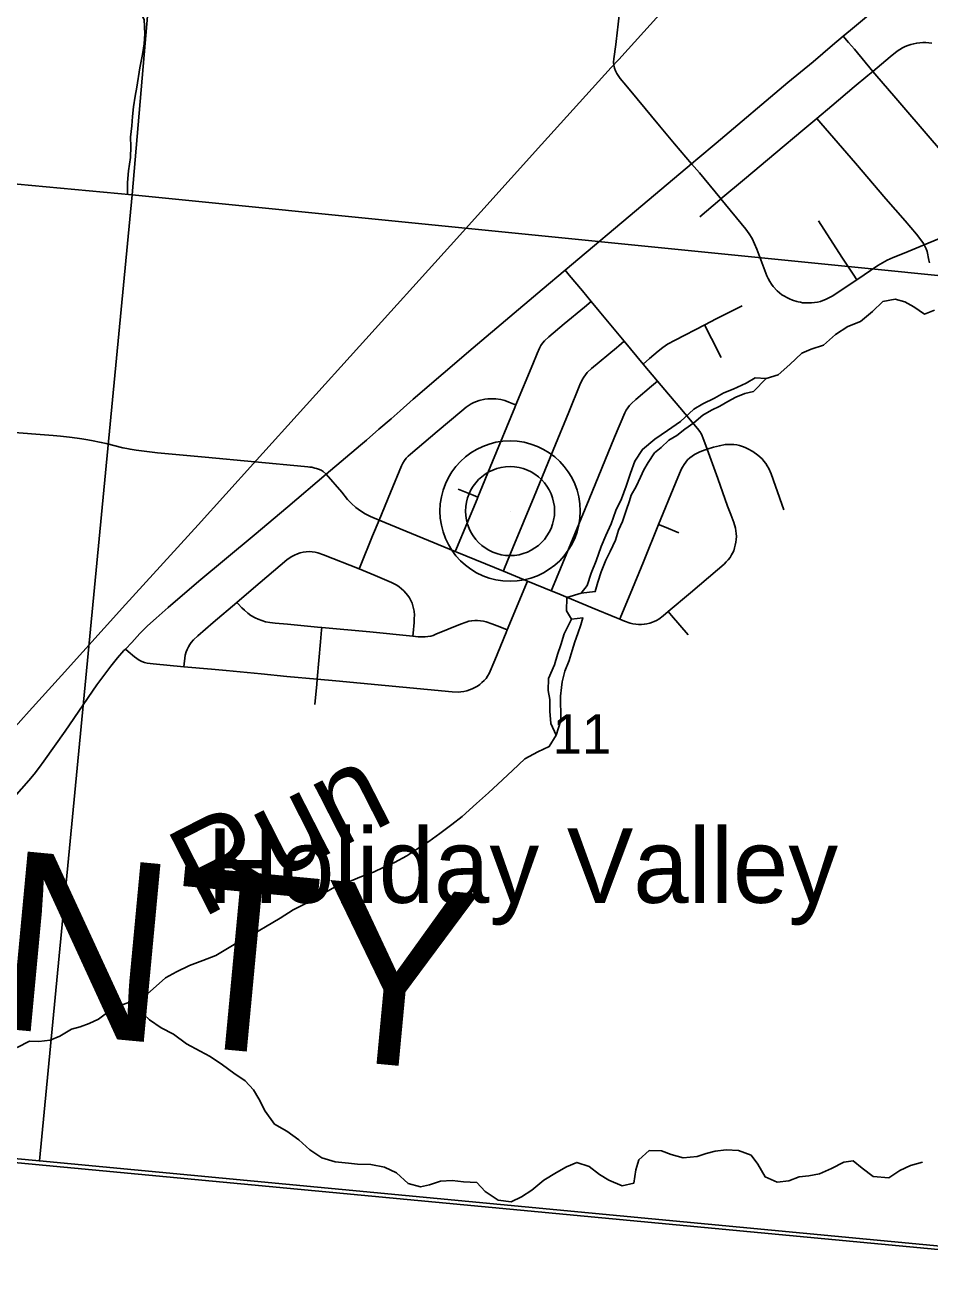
# Model space of a CAD drawing. Extents: x 0 to 1134, y 0 to 440.
# Drawn here: x 838.269 to 839.228, y 357.514 to 358.846 of the extents above; entities that cross this region are included whole.
import ezdxf

# ---------------------------------------------------------------- set-up
doc = ezdxf.new("R2010")
doc.units = 0
for name, color, linetype in [('GM_X_County_Road', 7, 'Continuous'), ('GM_X_County_Text', 7, 'Continuous'), ('GM_X_Minor_Lake', 7, 'Continuous'), ('GM_X_Minor_River', 7, 'Continuous'), ('GM_X_Minor_River_Text', 7, 'Continuous'), ('GM_X_Rail_Line', 7, 'Continuous'), ('GM_X_Section', 7, 'Continuous'), ('GM_X_Section_Text', 7, 'Continuous'), ('GM_X_Township', 7, 'Continuous'), ('GM_X_Township_Road', 7, 'Continuous'), ('GM_X_Unincorporated', 7, 'Continuous'), ('GM_X_Unincorporated_Location', 7, 'Continuous'), ('GM_X_Unincorporated_Text', 7, 'Continuous'), ('SH_Cut_Line', 7, 'Continuous')]:
    doc.layers.add(name, color=color, linetype=linetype)

msp = doc.modelspace()

# ---------------------------------------------------------------- linework, layer by layer
at = {"layer": 'GM_X_County_Road'}
for points in [[(839.1364, 358.8339), (839.1442, 358.8404), (839.2059, 358.8923), (839.2297, 358.9122), (839.2323, 358.9144)], [(838.9755, 358.6986), (838.9821, 358.7043), (839.0016, 358.7206), (839.0776, 358.7847), (839.1044, 358.8069), (839.1251, 358.8245), (839.1364, 358.8339)], [(838.8414, 358.5858), (838.9238, 358.6552), (838.9755, 358.6986)], [(838.5879, 358.3697), (838.6244, 358.4002), (838.6309, 358.4058), (838.6439, 358.4172), (838.6569, 358.4284), (838.6663, 358.4367), (838.6802, 358.4492), (838.7439, 358.5034), (838.8172, 358.5654), (838.8414, 358.5858)], [(838.2073, 358.4176), (838.2847, 358.4116), (838.2985, 358.4105), (838.3062, 358.4098), (838.3156, 358.4088), (838.3239, 358.4078), (838.3288, 358.4071), (838.333, 358.4065), (838.339, 358.4054), (838.3494, 358.4033), (838.3545, 358.4022), (838.3723, 358.3976), (838.3766, 358.3967), (838.38, 358.396), (838.3863, 358.395), (838.3949, 358.3939), (838.409, 358.3923), (838.4598, 358.3878), (838.5124, 358.3827), (838.565, 358.3779), (838.5686, 358.3775), (838.5707, 358.3772), (838.5729, 358.3769), (838.574, 358.3766), (838.575, 358.3764), (838.576, 358.3761), (838.5778, 358.3755), (838.5797, 358.3748), (838.5825, 358.3737), (838.5849, 358.3723), (838.5879, 358.3697)], [(838.375, 358.1841), (838.3817, 358.1913), (838.3905, 358.2007), (838.3986, 358.2087), (838.4076, 358.217), (838.4203, 358.2283), (838.4528, 358.2562), (838.5115, 358.3051), (838.5473, 358.335), (838.5879, 358.3697)], [(838.2572, 358.027), (838.2728, 358.0448), (838.2782, 358.0514), (838.2838, 358.0589), (838.2886, 358.0653), (838.311, 358.0972), (838.3449, 358.1461), (838.3596, 358.166), (838.3668, 358.175), (838.3735, 358.1826), (838.375, 358.1841)]]:
    msp.add_lwpolyline(points, dxfattribs=at)
at = {"layer": 'GM_X_Minor_Lake'}
for points in [[(838.8583, 358.2435), (838.8648, 358.2514), (838.8691, 358.2646), (838.8742, 358.2778), (838.8796, 358.2929), (838.8847, 358.3046), (838.8902, 358.317), (838.8952, 358.331), (838.9011, 358.3434), (838.9061, 358.357), (838.9108, 358.3706), (838.9155, 358.3834), (838.9236, 358.3958), (838.9366, 358.4066), (838.95, 358.4159), (838.9637, 358.4256), (838.9778, 358.4387), (838.9874, 358.4443), (838.9999, 358.4502), (839.0098, 358.4558), (839.0197, 358.4598), (839.0334, 358.4661), (839.0429, 358.4716), (839.0546, 358.4711)], [(838.8583, 358.2435), (838.8734, 358.2452), (838.8762, 358.2551), (838.8797, 358.266), (838.8844, 358.2784), (838.889, 358.2875), (838.8948, 358.2995), (838.898, 358.3101), (838.9023, 358.3195), (838.9062, 358.3312), (838.9097, 358.3414), (838.9113, 358.3475), (838.9167, 358.3565), (838.9214, 358.3663), (838.9249, 358.3742), (838.9295, 358.3821), (838.9361, 358.3922), (838.9433, 358.3978), (838.9513, 358.4057), (838.9597, 358.4105), (838.9685, 358.4172), (838.978, 358.4239), (838.9876, 358.4322), (838.9967, 358.4373), (839.0055, 358.4418), (839.0138, 358.4466), (839.0226, 358.4511), (839.0321, 358.4551), (839.0412, 358.4573), (839.0546, 358.4711)], [(838.8482, 358.2158), (838.8403, 358.2002), (838.8368, 358.1885), (838.8333, 358.1783), (838.8301, 358.1673), (838.8239, 358.153), (838.8233, 358.1401), (838.8251, 358.1306), (838.8253, 358.1185), (838.8263, 358.1052), (838.8318, 358.093)], [(838.8318, 358.093), (838.8369, 358.1085), (838.8367, 358.1168), (838.8364, 358.1267), (838.8365, 358.1343), (838.8374, 358.1434), (838.8382, 358.1494), (838.841, 358.1608), (838.8456, 358.1721), (838.8488, 358.1826), (838.8516, 358.1917), (838.8547, 358.2007), (838.8582, 358.2098), (838.8602, 358.2174), (838.8482, 358.2158)]]:
    msp.add_lwpolyline(points, dxfattribs=at)
at = {"layer": 'GM_X_Minor_River'}
for points in [[(838.3855, 358.8731), (838.3896, 358.8619), (838.3948, 358.8516), (838.3958, 358.8365), (838.3949, 358.8259), (838.3932, 358.8145), (838.3904, 358.8005), (838.3871, 358.7801), (838.3855, 358.7703), (838.3835, 358.759), (838.3826, 358.7487), (838.3817, 358.7389), (838.3804, 358.7268), (838.3807, 358.7169), (838.3805, 358.7052), (838.3785, 358.6912), (838.3772, 358.6787), (838.3774, 358.6662)], [(838.3272, 357.7836), (838.3367, 357.7872), (838.3466, 357.7917), (838.3592, 357.8014), (838.3725, 357.8073), (838.3831, 357.8113), (838.3956, 357.8161), (838.4078, 357.8269), (838.4174, 357.8355), (838.4292, 357.8418), (838.4429, 357.8485), (838.4573, 357.854), (838.471, 357.8591), (838.4851, 357.8677), (838.495, 357.8736), (838.5117, 357.8825), (838.5235, 357.8895), (838.5391, 357.8988), (838.5529, 357.9077), (838.5665, 357.9144), (838.5772, 357.9215), (838.5901, 357.9278), (838.6016, 357.9344), (838.6145, 357.9384), (838.6255, 357.9432), (838.638, 357.9476), (838.649, 357.9528), (838.6604, 357.958), (838.6734, 357.965), (838.6841, 357.9721), (838.697, 357.9803), (838.7084, 357.9885), (838.7214, 357.9981), (838.7321, 358.0067), (838.7474, 358.0206), (838.76, 358.0318), (838.7699, 358.0411), (838.7856, 358.0553), (838.7986, 358.0677), (838.8123, 358.0751), (838.8245, 358.081), (838.8318, 358.093), (838.8263, 358.1052), (838.8253, 358.1185), (838.8251, 358.1306), (838.8233, 358.1401), (838.8239, 358.153), (838.8301, 358.1673), (838.8333, 358.1783), (838.8368, 358.1885), (838.8403, 358.2002), (838.8482, 358.2158), (838.8429, 358.2248), (838.8431, 358.2388), (838.8583, 358.2435), (838.8648, 358.2514), (838.8691, 358.2646), (838.8742, 358.2778), (838.8796, 358.2929), (838.8847, 358.3046), (838.8902, 358.317), (838.8952, 358.331), (838.9011, 358.3434), (838.9061, 358.357), (838.9108, 358.3706), (838.9155, 358.3834), (838.9236, 358.3958), (838.9366, 358.4066), (838.95, 358.4159), (838.9637, 358.4256), (838.9778, 358.4387), (838.9874, 358.4443), (838.9999, 358.4502), (839.0098, 358.4558), (839.0197, 358.4598), (839.0334, 358.4661), (839.0429, 358.4716), (839.0546, 358.4711), (839.0675, 358.4748), (839.0797, 358.486), (839.0923, 358.4979), (839.1022, 358.502), (839.1155, 358.5064), (839.1281, 358.5176), (839.1411, 358.5261), (839.1547, 358.5313), (839.1673, 358.5421), (839.1784, 358.5526), (839.1913, 358.5551), (839.2015, 358.5523), (839.2112, 358.5469), (839.2225, 358.5392), (839.2331, 358.5436)], [(838.3796, 357.81), (838.3887, 357.8025), (838.4006, 357.791), (838.413, 357.7825), (838.4261, 357.7759), (838.44, 357.7655), (838.4542, 357.7578), (838.4648, 357.7523), (838.4779, 357.7435), (838.4899, 357.7346), (838.5019, 357.7265), (838.5108, 357.7169), (838.5164, 357.7074), (838.5234, 357.6944), (838.533, 357.6806), (838.5462, 357.6729), (838.5589, 357.664), (838.5705, 357.6533), (838.5832, 357.6448), (838.5976, 357.6404), (838.6115, 357.6391), (838.6213, 357.6382), (838.6353, 357.6377), (838.65, 357.6349), (838.6624, 357.6287), (838.6748, 357.6175), (838.6879, 357.6139), (838.6974, 357.6161), (838.7092, 357.6201), (838.7217, 357.6207), (838.7337, 357.6194), (838.7477, 357.6185), (838.7567, 357.6089), (838.7705, 357.6), (838.7841, 357.598), (838.7952, 357.6035), (838.8062, 357.6106), (838.8188, 357.621), (838.8321, 357.6292), (838.8428, 357.6352), (838.8538, 357.6399), (838.867, 357.6356), (838.8778, 357.6271), (838.8876, 357.621), (838.9019, 357.6151), (838.9144, 357.618), (838.9165, 357.632), (838.9196, 357.6425), (838.9307, 357.6526), (838.9435, 357.6521), (838.9537, 357.6482), (838.9665, 357.6446), (838.9813, 357.646), (838.9911, 357.6492), (839.0006, 357.6518), (839.0123, 357.6532), (839.0252, 357.6526), (839.0387, 357.6475), (839.0458, 357.638), (839.0536, 357.6246), (839.0663, 357.6188), (839.0788, 357.6205), (839.0895, 357.6245), (839.0997, 357.6255), (839.1111, 357.6277), (839.124, 357.6336), (839.1369, 357.6402), (839.1468, 357.6416), (839.1565, 357.6339), (839.1681, 357.6251), (839.1847, 357.6234), (839.1965, 357.6312), (839.2076, 357.6367), (839.2204, 357.64)], [(838.2604, 357.7616), (838.2733, 357.7683), (838.2832, 357.7682), (838.2953, 357.7696), (838.3055, 357.7736), (838.3177, 357.781), (838.3272, 357.7836)]]:
    msp.add_lwpolyline(points, dxfattribs=at)
at = {"layer": 'GM_X_Rail_Line'}
msp.add_lwpolyline([(837.872, 357.6755), (838.0709, 357.8948), (838.0864, 357.912), (838.1309, 357.9613), (838.2285, 358.069), (838.2731, 358.1184), (838.3074, 358.1561), (838.3753, 358.2315), (838.4523, 358.316), (838.5109, 358.3809), (838.6232, 358.5053), (838.7198, 358.612), (838.8165, 358.719), (838.8903, 358.8008), (838.8984, 358.8093), (839.1238, 359.059), (839.4679, 359.4389)], dxfattribs=at)
at = {"layer": 'GM_X_Section'}
for points in [[(837.5184, 359.736), (838.4659, 359.6429), (838.3822, 358.6657), (837.4241, 358.7547)], [(839.4487, 359.5561), (839.4699, 359.5539), (839.3675, 358.5672), (838.3822, 358.6657), (838.4659, 359.6429)], [(837.4241, 358.7547), (838.3822, 358.6657), (838.2839, 357.6414), (837.3231, 357.7301)], [(839.3675, 358.5672), (839.2878, 357.5465), (838.2839, 357.6414), (838.3822, 358.6657)]]:
    msp.add_lwpolyline(points, close=True, dxfattribs=at)
at = {"layer": 'GM_X_Township'}
msp.add_lwpolyline([(839.5899, 357.5143), (837.799, 357.6829), (837.6618, 357.6958), (837.4578, 357.7151), (837.4468, 357.7161), (837.4263, 357.718), (837.4114, 357.7196), (837.3087, 357.7292), (835.8437, 357.8674), (835.1657, 357.9387)], dxfattribs=at)
at = {"layer": 'GM_X_Township_Road'}
for p, q in [((838.904, 358.5106), (838.9242, 358.4863)), ((838.9242, 358.4863), (838.9393, 358.4683)), ((838.644, 358.3209), (838.7249, 358.2876)), ((838.7759, 358.2666), (838.8014, 358.2562)), ((838.8014, 358.2562), (838.8266, 358.2458))]:
    msp.add_line(p, q, dxfattribs=at)
for points in [[(838.896, 358.8314), (838.8964, 358.8344), (838.8981, 358.8498), (838.8994, 358.8621), (838.9014, 358.8837), (838.9079, 358.958), (838.9114, 358.9982), (838.914, 359.0291), (838.9194, 359.0909), (838.9243, 359.1497), (838.9348, 359.2703), (838.9387, 359.3167), (838.9444, 359.3817), (838.9542, 359.4961), (838.9596, 359.5518), (838.9632, 359.5888), (838.9639, 359.5988)], [(839.1678, 358.7966), (839.1482, 358.8202), (839.1421, 358.8273), (839.1364, 358.8339)], [(838.9755, 358.6986), (838.9575, 358.7199), (838.9415, 358.7389), (838.9177, 358.7676), (838.9057, 358.7819), (838.8999, 358.7892), (838.8964, 358.7944), (838.8949, 358.7972), (838.8937, 358.8002), (838.893, 358.8034), (838.8928, 358.8066), (838.893, 358.8098), (838.8952, 358.8252), (838.896, 358.8314)], [(839.2304, 358.8265), (839.2272, 358.827), (839.224, 358.8272), (839.2208, 358.8272), (839.2176, 358.827), (839.2144, 358.8266), (839.2112, 358.826), (839.2081, 358.8252), (839.205, 358.8241), (839.202, 358.8229), (839.1991, 358.8215), (839.1963, 358.8199), (839.1936, 358.818), (839.1861, 358.8121), (839.1678, 358.7966)], [(839.1083, 358.7467), (839.1244, 358.7603), (839.1481, 358.7804), (839.1625, 358.7922), (839.1678, 358.7966)], [(839.3027, 358.6401), (839.2977, 358.6459), (839.2308, 358.7235), (839.1923, 358.7681), (839.17, 358.794), (839.1678, 358.7966)], [(839.0065, 358.6615), (839.0317, 358.6823), (839.065, 358.7103), (839.0935, 358.7343), (839.1083, 358.7467)], [(839.2221, 358.6128), (839.2214, 358.614), (839.2197, 358.6166), (839.214, 358.624), (839.202, 358.6383), (839.1816, 358.6617), (839.1492, 358.6994), (839.1126, 358.7417), (839.1083, 358.7467)], [(839.0065, 358.6615), (839.0054, 358.6628), (838.9838, 358.689), (838.9755, 358.6986)], [(838.9842, 358.6423), (839.0054, 358.6605), (839.0065, 358.6615)], [(839.0871, 358.5526), (839.0825, 358.5542), (839.0795, 358.5554), (839.0767, 358.5568), (839.0739, 358.5583), (839.0712, 358.5599), (839.0687, 358.5618), (839.0663, 358.5639), (839.0621, 358.5685), (839.0602, 358.5711), (839.0584, 358.5738), (839.0566, 358.5769), (839.0552, 358.58), (839.0448, 358.6082), (839.0424, 358.6138), (839.0397, 358.6193), (839.0365, 358.6245), (839.0329, 358.6294), (839.0065, 358.6615)], [(839.1507, 358.5758), (839.1468, 358.5818), (839.135, 358.5997), (839.1102, 358.6382)], [(839.2221, 358.6128), (839.2368, 358.6189), (839.243, 358.6214), (839.249, 358.6236), (839.2571, 358.6263), (839.2648, 358.6288), (839.3027, 358.6401)], [(839.1507, 358.5758), (839.1732, 358.5907), (839.1779, 358.5936), (839.1828, 358.5964), (839.1894, 358.5992), (839.2008, 358.6039), (839.2221, 358.6128)], [(839.2279, 358.5935), (839.2273, 358.5965), (839.2254, 358.6057), (839.2243, 358.6086), (839.223, 358.6113), (839.2221, 358.6128)], [(838.8414, 358.5858), (838.8458, 358.5805), (838.8598, 358.5639), (838.8691, 358.5526)], [(839.0871, 358.5526), (839.0887, 358.5522), (839.0909, 358.5518), (839.0933, 358.5514), (839.0966, 358.5512), (839.0996, 358.5512), (839.1026, 358.5512), (839.1059, 358.5515), (839.1091, 358.552), (839.1122, 358.5528), (839.1181, 358.555), (839.1225, 358.5572), (839.1246, 358.5585), (839.1507, 358.5758)], [(838.7891, 358.443), (838.807, 358.4862), (838.8117, 358.4976), (838.8142, 358.5033), (838.8158, 358.506), (838.8175, 358.5085), (838.8195, 358.5109), (838.824, 358.5152), (838.8405, 358.5291), (838.8621, 358.5468), (838.8691, 358.5526)], [(838.8691, 358.5526), (838.8775, 358.5424), (838.904, 358.5106)], [(838.9894, 358.5279), (839.0017, 358.5342), (839.0292, 358.5482)], [(838.9242, 358.4863), (838.9309, 358.4921), (838.9402, 358.5001), (838.9451, 358.5039), (838.9501, 358.5073), (838.9581, 358.5118), (838.9894, 358.5279)], [(838.9894, 358.5279), (838.9904, 358.5259), (838.9967, 358.5136), (839.007, 358.4932)], [(838.7759, 358.2666), (838.7772, 358.2699), (838.7861, 358.2914), (838.8086, 358.346), (838.8286, 358.395), (838.8453, 358.4352), (838.8569, 358.4642), (838.8595, 358.4698), (838.8611, 358.4725), (838.8629, 358.475), (838.8649, 358.4774), (838.8694, 358.4817), (838.8958, 358.5035), (838.8982, 358.5055), (838.904, 358.5106)], [(838.8266, 358.2458), (838.8279, 358.249), (838.867, 358.343), (838.8939, 358.4089), (838.9047, 358.4346), (838.9061, 358.4373), (838.9078, 358.4399), (838.9098, 358.4423), (838.9119, 358.4446), (838.9165, 358.4488), (838.9329, 358.4628), (838.9393, 358.4683)], [(838.9393, 358.4683), (838.947, 358.459), (838.9632, 358.4402), (838.9819, 358.4182), (838.9843, 358.415), (838.986, 358.412), (838.9886, 358.4055), (838.992, 358.3961)], [(838.644, 358.3209), (838.6561, 358.35), (838.6679, 358.3786), (838.6694, 358.3814), (838.6711, 358.384), (838.6729, 358.3864), (838.675, 358.3887), (838.6773, 358.3908), (838.7058, 358.4147), (838.7317, 358.4369), (838.7366, 358.4407), (838.7417, 358.4441), (838.7445, 358.4455), (838.7474, 358.4467), (838.7503, 358.4476), (838.7563, 358.449), (838.7594, 358.4494), (838.7638, 358.4496), (838.768, 358.4494), (838.7731, 358.4487), (838.7773, 358.4476), (838.7818, 358.4459), (838.787, 358.4438), (838.7891, 358.443)], [(838.7488, 358.3452), (838.7643, 358.3832), (838.788, 358.4404), (838.7891, 358.443)], [(838.9406, 358.3164), (838.9584, 358.3602), (838.9645, 358.3744), (838.9659, 358.3772), (838.9675, 358.3799), (838.9693, 358.3824), (838.9713, 358.3847), (838.9736, 358.3868), (838.9761, 358.3887), (838.9787, 358.3904), (838.9842, 358.3932), (838.99, 358.3955), (838.992, 358.3961)], [(838.992, 358.3961), (838.9989, 358.3982), (839.005, 358.3998), (839.0111, 358.4009), (839.0142, 358.4012), (839.0173, 358.4012), (839.0204, 358.401), (839.0234, 358.4006), (839.0265, 358.4), (839.0295, 358.399), (839.0324, 358.3979), (839.0352, 358.3966), (839.0406, 358.3936), (839.0456, 358.3899), (839.0502, 358.3857), (839.0522, 358.3834), (839.0541, 358.3809), (839.0558, 358.3783), (839.0573, 358.3756), (839.0598, 358.3699), (839.0712, 358.3377), (839.0734, 358.3319)], [(838.992, 358.3961), (839.0032, 358.3649), (839.0136, 358.3356), (839.017, 358.327), (839.0202, 358.3183), (839.022, 358.3125), (839.0225, 358.3095), (839.0229, 358.3066), (839.023, 358.3035), (839.0229, 358.3005), (839.0225, 358.2975), (839.0219, 358.2943), (839.0212, 358.2915), (839.0202, 358.2884)], [(838.5879, 358.3697), (838.6045, 358.3505), (838.6107, 358.3429), (838.6148, 358.3384), (838.6194, 358.3344), (838.6243, 358.3307), (838.6295, 358.3275), (838.6349, 358.3247), (838.644, 358.3209)], [(838.7249, 358.2876), (838.7263, 358.2909), (838.748, 358.3431), (838.7488, 358.3452)], [(838.7278, 358.3537), (838.7439, 358.3472), (838.7488, 358.3452)], [(838.6228, 358.2691), (838.6239, 358.2717), (838.6371, 358.3042), (838.644, 358.3209)], [(838.8993, 358.2158), (838.9005, 358.2188), (838.9102, 358.2423), (838.9244, 358.2768), (838.9406, 358.3164)], [(838.9406, 358.3164), (838.9468, 358.3138), (838.9619, 358.3074)], [(838.9507, 358.2239), (838.9742, 358.2438), (839.003, 358.2681), (839.0101, 358.2743), (839.0123, 358.2766), (839.0144, 358.2789), (839.0163, 358.2814), (839.018, 358.284), (839.0189, 358.2857), (839.0202, 358.2884)], [(838.4933, 358.2337), (838.5109, 358.2486), (838.5321, 358.2667), (838.5464, 358.2788), (838.5489, 358.2807), (838.5516, 358.2824), (838.5544, 358.2839), (838.5574, 358.2851), (838.5604, 358.2861), (838.5635, 358.2868), (838.5667, 358.2873), (838.5699, 358.2875), (838.573, 358.2873), (838.5762, 358.2868), (838.5793, 358.2862), (838.5853, 358.2842), (838.6228, 358.2691)], [(838.7249, 358.2876), (838.7267, 358.2869), (838.7759, 358.2666)], [(838.6228, 358.2691), (838.6401, 358.262), (838.6573, 358.2548), (838.6601, 358.2534), (838.6628, 358.2518), (838.6655, 358.25), (838.6679, 358.248), (838.6703, 358.2459), (838.6725, 358.2436), (838.6745, 358.2411), (838.6763, 358.2385), (838.6778, 358.2356), (838.679, 358.2327), (838.6804, 358.2287), (838.6812, 358.2245), (838.6815, 358.22), (838.6814, 358.2167), (838.6812, 358.2125), (838.6802, 358.2011), (838.6799, 358.1979)], [(838.7799, 358.2044), (838.8003, 358.2536), (838.8014, 358.2562)], [(838.8266, 358.2458), (838.8328, 358.2433), (838.8701, 358.2279), (838.8959, 358.2172), (838.8993, 358.2158)], [(838.437, 358.1654), (838.4374, 358.1685), (838.4381, 358.1744), (838.4386, 358.1776), (838.4394, 358.1811), (838.4405, 358.1838), (838.4419, 358.1866), (838.4435, 358.1891), (838.4448, 358.191), (838.4472, 358.1938), (838.4517, 358.1982), (838.4682, 358.2125), (838.4933, 358.2337)], [(838.4933, 358.2337), (838.4948, 358.232), (838.4984, 358.228), (838.5012, 358.2254), (838.5049, 358.2222), (838.5081, 358.2199), (838.5125, 358.2174), (838.5157, 358.2159), (838.5197, 358.2144), (838.5238, 358.2132), (838.5282, 358.2124), (838.5339, 358.2117), (838.5468, 358.2105)], [(838.9341, 358.2127), (838.936, 358.2135), (838.9383, 358.2146), (838.9407, 358.216), (838.9454, 358.2194), (838.9507, 358.2239)], [(838.9507, 358.2239), (838.9542, 358.2199), (838.9719, 358.1993)], [(838.5468, 358.2105), (838.5787, 358.2074), (838.5833, 358.207)], [(838.6799, 358.1979), (838.6856, 358.1973), (838.6894, 358.1971), (838.6928, 358.1971), (838.6959, 358.1974), (838.699, 358.1979), (838.7015, 358.1987), (838.7043, 358.1998), (838.7306, 358.2106), (838.7364, 358.2128), (838.7394, 358.2136), (838.7424, 358.2142), (838.7455, 358.2145), (838.7486, 358.2145), (838.7517, 358.2142), (838.7548, 358.2138), (838.7578, 358.2131), (838.7637, 358.2111), (838.7723, 358.2076), (838.7799, 358.2044)], [(838.8993, 358.2158), (838.9045, 358.2137), (838.9103, 358.2118), (838.9133, 358.2111), (838.9163, 358.2106), (838.9193, 358.2102), (838.9223, 358.2102), (838.9253, 358.2105), (838.9282, 358.211), (838.9311, 358.2118), (838.9341, 358.2127)], [(838.5785, 358.1523), (838.582, 358.192), (838.5831, 358.2044), (838.5833, 358.207)], [(838.5785, 358.1523), (838.5981, 358.1505), (838.7216, 358.1388), (838.7278, 358.1386), (838.7309, 358.1388), (838.7339, 358.1392), (838.737, 358.1399), (838.7399, 358.1408), (838.7428, 358.1419), (838.7456, 358.1433), (838.7483, 358.1448), (838.7508, 358.1466), (838.7532, 358.1486), (838.7554, 358.1507), (838.7575, 358.153), (838.759, 358.1554), (838.7607, 358.1583), (838.767, 358.1724), (838.7788, 358.2017), (838.7799, 358.2044)], [(838.5833, 358.207), (838.6342, 358.2023), (838.6799, 358.1979)], [(838.375, 358.1841), (838.3779, 358.1817), (838.3846, 358.176), (838.387, 358.1741), (838.3896, 358.1724), (838.3924, 358.1711), (838.3953, 358.17), (838.3983, 358.1693), (838.4045, 358.1684), (838.437, 358.1654)], [(838.437, 358.1654), (838.4663, 358.1628), (838.4818, 358.1614), (838.5189, 358.1578), (838.5461, 358.1552), (838.5785, 358.1523)], [(838.5759, 358.1255), (838.578, 358.1469), (838.5785, 358.1523)]]:
    msp.add_lwpolyline(points, dxfattribs=at)
at = {"layer": 'GM_X_Unincorporated'}
msp.add_lwpolyline([(839.5899, 357.5143), (837.799, 357.6829), (837.6618, 357.6958), (837.4578, 357.7151), (837.4468, 357.7161), (837.4263, 357.718), (837.4114, 357.7196), (837.3087, 357.7292), (835.8437, 357.8674), (835.1657, 357.9387)], dxfattribs=at)
for radius in [0.0744, 0.0472]:
    msp.add_circle((838.783, 358.3305), radius, dxfattribs=at)
at = {"layer": 'GM_X_Unincorporated_Location'}
msp.add_line((838.783, 358.3305), (838.783, 358.3305), dxfattribs=at)
at = {"layer": 'SH_Cut_Line'}
for points in [[(834.6028, 361.9945), (834.5417, 361.3013), (834.5402, 361.279), (834.4289, 360.039), (834.4188, 359.8449), (834.3527, 359.1244), (834.3462, 359.0437), (834.3448, 359.0281), (834.3438, 359.02), (834.3396, 358.9758), (834.278, 358.3392), (834.2504, 358.0272), (835.1657, 357.9387), (835.8437, 357.8674), (837.3087, 357.7292), (837.4114, 357.7196), (837.4263, 357.718), (837.4468, 357.7161), (837.4578, 357.7151), (837.6618, 357.6958), (837.799, 357.6829), (839.5899, 357.5143)], [(839.5899, 357.5143), (837.799, 357.6829), (837.6618, 357.6958), (837.4578, 357.7151), (837.4468, 357.7161), (837.4263, 357.718), (837.4114, 357.7196), (837.3087, 357.7292), (835.8437, 357.8674), (835.1657, 357.9387)]]:
    msp.add_lwpolyline(points, dxfattribs=at)

# ---------------------------------------------------------------- texts
at = {"layer": 'GM_X_County_Text'}
msp.add_text('CLARK COUNTY', height=0.189394, rotation=354.6384, dxfattribs=at).set_placement((836.7618, 357.9209))
at = {"layer": 'GM_X_Minor_River_Text'}
msp.add_text('Run', height=0.09469, rotation=26.9991, dxfattribs=at).set_placement((838.4558, 357.8982))
at = {"layer": 'GM_X_Section_Text'}
msp.add_text('11', height=0.04186, rotation=0, dxfattribs=at).set_placement((838.8282, 358.0732))
at = {"layer": 'GM_X_Unincorporated_Text'}
msp.add_text('Holiday Valley', height=0.078977, rotation=0, dxfattribs=at).set_placement((838.4617, 357.9151))

doc.saveas('drawing.dxf')
